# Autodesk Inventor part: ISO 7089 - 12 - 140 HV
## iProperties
Created: 2001-12
Part Number: ISO 7089 - 12 - 140 HV
Catalog Web Link: file:///F:/Cad/Autodesk/Inventor 5/Content/Iso/index.htm?doNavigateId=8E0024B3-6CA5-42D3-99D9-F0092A40B40C|74B1A93DC0A940FBB961F80085F4CFD|true
Description: Washer
Document SubType Name: Standard Catalog Part
Standard: ISO 7089 - 12 - 140 HV
Designer: Tobben
Density: 1 g/cm^3
Control State: 0
Master: False
Checked Out: False
Shininess: 64.0
Angle Display Precision: 2
Document Length Units: 11269
Document Angle Units: 11279
Document Time Units: 11290
Document Mass Units: 11283
Document Length Units Precision: 3
Document Angle Units Precision: 2
Compacted: True
CLASSIFICATION: 31161807 un/spsc
MANUFACTURER: ISO Standard System
Density: 0.0
Volumn: 0.0
Area: 0.0
PropertySet Name: Model Information
Author: Tobben
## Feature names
1. Base1
